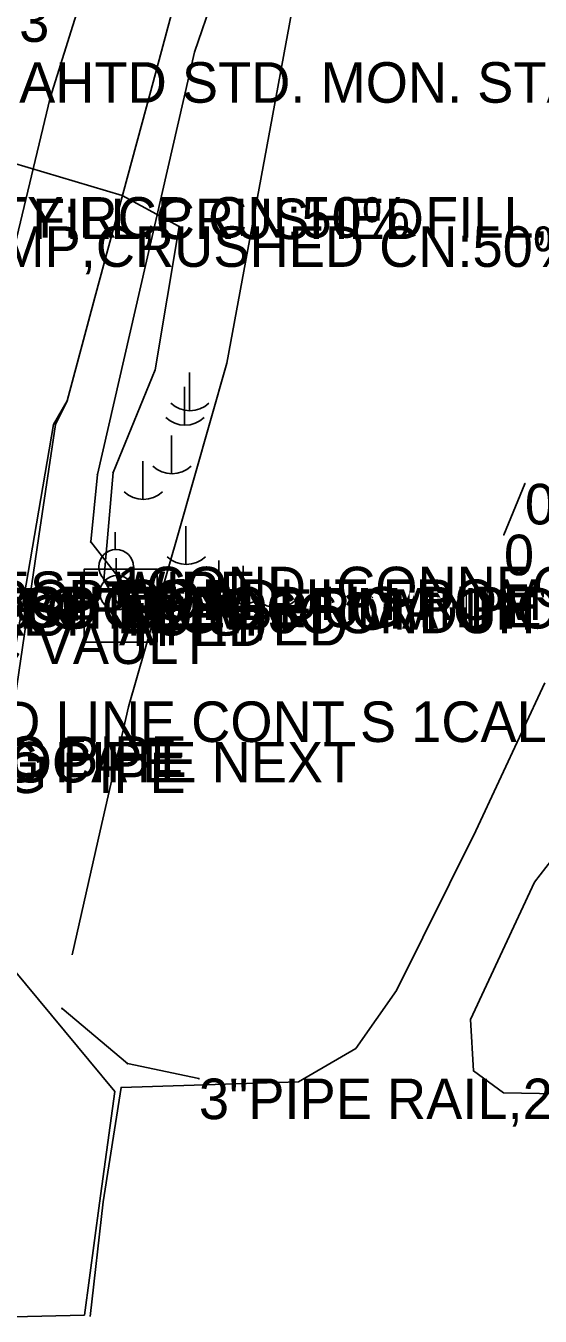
# Model space of a CAD drawing. Extents: x 997398 to 1003416, y 334596 to 337085.
# Drawn here: x 999274.2 to 999337.6, y 335481.5 to 335640.6 of the extents above; entities that cross this region are included whole.
import ezdxf

# ---------------------------------------------------------------- set-up
doc = ezdxf.new("R2010")
doc.units = 0
for name, color, linetype in [('S_DITCHLINE', 7, 'Continuous'), ('S_EDGE_PAVEMENT', 7, 'Continuous'), ('S_ELECTRIC_UTILITIES_ANNOT', 7, 'Continuous'), ('S_FENCE', 7, 'Continuous'), ('S_FENCE_ANNOT', 7, 'Continuous'), ('S_FIBER_OPTIC_CABLE', 7, 'Continuous'), ('S_FIBER_OPTIC_CABLE_ANNOT', 7, 'Continuous'), ('S_GAS_UTILITIES_ANNOT', 7, 'Continuous'), ('S_MANHOLE_ANNOT', 7, 'Continuous'), ('S_MISC_TOPO_POINT', 7, 'Continuous'), ('S_MSC_PT_SYM', 7, 'Continuous'), ('S_PAVEMENT_CROWN', 7, 'Continuous'), ('S_PRIMARY_CTL_ANNOT', 7, 'Continuous'), ('S_SANITARY_SEWER_ANNOT', 7, 'Continuous'), ('S_SIDE_DRAIN_ANNOT', 7, 'Continuous'), ('S_SIGN', 7, 'Continuous'), ('S_SIGN_ANNOT', 7, 'Continuous'), ('S_STORM_SEWER_ANNOT', 7, 'Continuous'), ('S_TELEPHONE_UTILITIES', 7, 'Continuous'), ('S_TELEPHONE_UTILITIES_ANNOT', 7, 'Continuous'), ('S_UTILITY_POLE', 7, 'Continuous'), ('S_UTILITY_POLE_ANNOT', 7, 'Continuous'), ('S_UTL_PT_SYM', 7, 'Continuous')]:
    doc.layers.add(name, color=color, linetype=linetype)

msp = doc.modelspace()

# ---------------------------------------------------------------- linework, layer by layer
at = {"layer": 'S_DITCHLINE'}
msp.add_lwpolyline([(999279.93, 335526.04), (999283.42, 335541.33), (999286.91, 335556.62), (999292.97, 335577.81), (999299.03, 335599), (999303, 335620.58), (999306.97, 335642.16), (999314.07, 335652.72)], dxfattribs=at)
at = {"layer": 'S_EDGE_PAVEMENT'}
for points in [[(999352.59, 335804.28), (999348.8, 335795.55), (999343.98, 335783.6), (999339.17, 335771.64), (999334.35, 335759.69), (999329.54, 335747.73), (999324.76, 335734.99), (999319.98, 335722.25), (999315.21, 335709.51), (999310.43, 335696.77), (999306.09, 335683.91), (999301.75, 335671.05), (999297.41, 335658.19), (999293.07, 335645.33), (999289.63, 335632.59), (999286.2, 335619.85), (999282.76, 335607.12), (999279.33, 335594.38)], [(999277.63, 335591.45), (999279.33, 335594.38)], [(999277.88, 335591.43), (999279.33, 335594.38)], [(999250.53, 335290.61), (999251.9, 335310.31), (999253.28, 335330), (999254.66, 335349.69), (999256.03, 335369.39), (999256.96, 335383.69), (999257.89, 335397.99), (999259.31, 335422.72), (999260.17, 335436.32), (999261.04, 335449.92), (999261.9, 335463.52), (999262.77, 335477.12), (999265.06, 335501.55), (999266.67, 335519.12), (999268.27, 335536.68), (999270.61, 335550.38), (999272.95, 335564.07), (999275.29, 335577.76), (999277.63, 335591.45)], [(999268.87, 335320.6), (999263.53, 335329.26), (999260.4, 335340), (999260.03, 335350.15), (999261.25, 335369.32), (999262.19, 335383.58), (999263.12, 335397.84), (999266.91, 335402.13), (999261.38, 335422.51), (999262.14, 335435.92), (999262.89, 335449.33), (999263.64, 335462.75), (999264.4, 335476.16), (999272.66, 335481.44), (999281.46, 335481.65), (999283.33, 335495.44), (999285.2, 335509.23), (999269.56, 335528.03), (999269.81, 335536.47), (999271.83, 335550.21), (999273.84, 335563.95), (999275.86, 335577.69), (999277.88, 335591.43)], [(999282.16, 335481.48), (999283.77, 335495.62), (999285.97, 335509.72), (999307.86, 335510.4), (999314.93, 335514.53), (999319.93, 335521.66), (999329.71, 335541.35), (999338.23, 335559.58)], [(999345.33, 335545.87), (999336.92, 335535.03), (999329.07, 335518.09), (999329.41, 335511.74), (999333.12, 335509.03), (999344.25, 335508.86)]]:
    msp.add_lwpolyline(points, dxfattribs=at)
at = {"layer": 'S_FENCE'}
for p, q in [((999286.76, 335512.65), (999278.7, 335519.45)), ((999295.57, 335510.8), (999286.76, 335512.65))]:
    msp.add_line(p, q, dxfattribs=at)
at = {"layer": 'S_FIBER_OPTIC_CABLE'}
for p, q in [((999295.04, 335637.34), (999313.68, 335692.48)), ((999283.06, 335585.29), (999295.04, 335637.34)), ((999286.13, 335619.67), (999256.41, 335628.49)), ((999293.13, 335615.87), (999286.13, 335619.67)), ((999290.19, 335598.19), (999293.13, 335615.87)), ((999285.01, 335585.53), (999290.19, 335598.19)), ((999282.24, 335576.97), (999283.06, 335585.29)), ((999283.84, 335572.27), (999285.01, 335585.53)), ((999285.88, 335572.34), (999282.24, 335576.97)), ((999285.71, 335569.2), (999283.84, 335572.27)), ((999285.67, 335571.14), (999285.71, 335569.2))]:
    msp.add_line(p, q, dxfattribs=at)
at = {"layer": 'S_MSC_PT_SYM'}
for points in [[(999335.75, 335584.13), (999335.75, 335584.18), (999335.75, 335584.13), (999335.7, 335584.13), (999335.75, 335584.13), (999335.75, 335584.08), (999335.75, 335584.13), (999335.8, 335584.13)], [(999333.17, 335577.86), (999333.17, 335577.91), (999333.17, 335577.86), (999333.12, 335577.86), (999333.17, 335577.86), (999333.17, 335577.81), (999333.17, 335577.86), (999333.22, 335577.86)], [(999278.7, 335519.45), (999278.7, 335519.5), (999278.7, 335519.45), (999278.65, 335519.45), (999278.7, 335519.45), (999278.7, 335519.4), (999278.7, 335519.45), (999278.75, 335519.45)], [(999286.76, 335512.65), (999286.76, 335512.7), (999286.76, 335512.65), (999286.71, 335512.65), (999286.76, 335512.65), (999286.76, 335512.6), (999286.76, 335512.65), (999286.81, 335512.65)], [(999295.57, 335510.8), (999295.57, 335510.85), (999295.57, 335510.8), (999295.52, 335510.8), (999295.57, 335510.8), (999295.57, 335510.75), (999295.57, 335510.8), (999295.62, 335510.8)]]:
    msp.add_lwpolyline(points, dxfattribs=at)
at = {"layer": 'S_PAVEMENT_CROWN'}
msp.add_lwpolyline([(999240.93, 335269.15), (999242.42, 335292.45), (999243.36, 335312.31), (999244.3, 335332.17), (999245.73, 335356.52), (999247.17, 335380.88), (999248.33, 335401.35), (999249.49, 335421.83), (999250.52, 335439.55), (999251.54, 335457.27), (999252.57, 335474.99), (999253.6, 335492.71), (999255.46, 335505.53), (999257.33, 335518.35), (999259.19, 335531.16), (999261.06, 335543.98), (999262.92, 335556.8), (999264.79, 335569.61), (999266.65, 335582.43), (999268.52, 335595.25), (999272.87, 335613.5), (999277.22, 335631.74), (999281.77, 335646.2)], dxfattribs=at)
at = {"layer": 'S_SIGN'}
msp.add_line((999333.17, 335577.86), (999335.75, 335584.13), dxfattribs=at)
at = {"layer": 'S_TELEPHONE_UTILITIES'}
msp.add_lwpolyline([(999281.42, 335564.61), (999281.42, 335573.61), (999290.42, 335573.61), (999290.42, 335564.61)], close=True, dxfattribs=at)
at = {"layer": 'S_UTILITY_POLE'}
for p, q in [((999294.4, 335597.85), (999294.4, 335593.12)), ((999293.78, 335596.08), (999293.78, 335591.35)), ((999292.2, 335590.09), (999292.2, 335585.36)), ((999288.67, 335586.92), (999288.67, 335582.19)), ((999293.95, 335578.9), (999293.95, 335574.17)), ((999285.24, 335576.05), (999285.24, 335578.16)), ((999285.37, 335572.85), (999285.37, 335574.96)), ((999298.02, 335574.67), (999298.02, 335569.95)), ((999301.04, 335574.04), (999301.04, 335569.32)), ((999305.12, 335573.56), (999305.12, 335568.83))]:
    msp.add_line(p, q, dxfattribs=at)
for centre in [(999285.37, 335573.91), (999285.49, 335570.71)]:
    msp.add_circle(centre, 2.13, dxfattribs=at)
for centre in [(999294.46, 335596.55), (999293.85, 335594.77), (999292.26, 335588.79), (999288.73, 335585.62), (999294.02, 335577.6), (999298.09, 335573.37), (999301.11, 335572.74), (999305.18, 335572.26)]:
    msp.add_arc(centre, 3.41, 226.3972, 313.6028, dxfattribs=at)
at = {"layer": 'S_UTL_PT_SYM'}
for points in [[(999295.04, 335637.34), (999295.04, 335637.39), (999295.04, 335637.34), (999294.99, 335637.34), (999295.04, 335637.34), (999295.04, 335637.29), (999295.04, 335637.34), (999295.09, 335637.34)], [(999286.13, 335619.67), (999286.13, 335619.72), (999286.13, 335619.67), (999286.08, 335619.67), (999286.13, 335619.67), (999286.13, 335619.62), (999286.13, 335619.67), (999286.18, 335619.67)], [(999293.13, 335615.87), (999293.13, 335615.92), (999293.13, 335615.87), (999293.08, 335615.87), (999293.13, 335615.87), (999293.13, 335615.82), (999293.13, 335615.87), (999293.18, 335615.87)], [(999290.19, 335598.19), (999290.19, 335598.24), (999290.19, 335598.19), (999290.14, 335598.19), (999290.19, 335598.19), (999290.19, 335598.14), (999290.19, 335598.19), (999290.24, 335598.19)], [(999283.06, 335585.29), (999283.06, 335585.34), (999283.06, 335585.29), (999283.01, 335585.29), (999283.06, 335585.29), (999283.06, 335585.24), (999283.06, 335585.29), (999283.11, 335585.29)], [(999285.01, 335585.53), (999285.01, 335585.58), (999285.01, 335585.53), (999284.96, 335585.53), (999285.01, 335585.53), (999285.01, 335585.48), (999285.01, 335585.53), (999285.06, 335585.53)], [(999282.24, 335576.97), (999282.24, 335577.02), (999282.24, 335576.97), (999282.19, 335576.97), (999282.24, 335576.97), (999282.24, 335576.92), (999282.24, 335576.97), (999282.29, 335576.97)], [(999283.84, 335572.27), (999283.84, 335572.32), (999283.84, 335572.27), (999283.79, 335572.27), (999283.84, 335572.27), (999283.84, 335572.22), (999283.84, 335572.27), (999283.89, 335572.27)], [(999285.88, 335572.34), (999285.88, 335572.39), (999285.88, 335572.34), (999285.83, 335572.34), (999285.88, 335572.34), (999285.88, 335572.29), (999285.88, 335572.34), (999285.93, 335572.34)], [(999285.67, 335571.14), (999285.67, 335571.19), (999285.67, 335571.14), (999285.62, 335571.14), (999285.67, 335571.14), (999285.67, 335571.09), (999285.67, 335571.14), (999285.72, 335571.14)], [(999285.71, 335569.2), (999285.71, 335569.25), (999285.71, 335569.2), (999285.66, 335569.2), (999285.71, 335569.2), (999285.71, 335569.15), (999285.71, 335569.2), (999285.76, 335569.2)]]:
    msp.add_lwpolyline(points, dxfattribs=at)

# ---------------------------------------------------------------- texts
at = {"layer": 'S_ELECTRIC_UTILITIES_ANNOT'}
for s, p in [('LOWEST WIRE', (999255.04, 335568.32)), ('CL48EW*32NSFOC VAULT', (999213.52, 335561.92))]:
    msp.add_text(s, height=5, dxfattribs=at).set_placement(p)
at = {"layer": 'S_FENCE_ANNOT'}
msp.add_text('3"PIPE RAIL,2.5\'H', height=5, dxfattribs=at).set_placement((999295.57, 335505.8))
at = {"layer": 'S_FIBER_OPTIC_CABLE_ANNOT'}
for s, p in [('CONDUIT FROM OH', (999285.88, 335567.34)), ('FEED FROM OH', (999285.67, 335566.14)), ('AT TPED', (999285.71, 335564.2))]:
    msp.add_text(s, height=5, dxfattribs=at).set_placement(p)
at = {"layer": 'S_GAS_UTILITIES_ANNOT'}
msp.add_text('1CALL SEZ DED LINE CONT S 1CALL', height=5, dxfattribs=at).set_placement((999224.76, 335552.3))
at = {"layer": 'S_MANHOLE_ANNOT'}
msp.add_text('TY:CONC BOTTOM OF MANHOLE', height=5, dxfattribs=at).set_placement((999241.48, 335566.28))
at = {"layer": 'S_MISC_TOPO_POINT'}
for p in [(999240.51, 335566.44), (999196.73, 335548), (999195.72, 335547.31), (999196.62, 335546)]:
    msp.add_text('SURFACE SHOT FOR UG PIPE', height=5, dxfattribs=at).set_placement(p)
at = {"layer": 'S_PRIMARY_CTL_ANNOT'}
for s, p in [('PN:3', (999262.27, 335638.62)), ('PD:AHTD STD. MON. STAMPED PN 3', (999262.27, 335631.12))]:
    msp.add_text(s, height=5, dxfattribs=at).set_placement(p)
at = {"layer": 'S_SANITARY_SEWER_ANNOT'}
msp.add_text('DI:6 TY:PVC TO W,C/N LOCATE NEXT', height=5, dxfattribs=at).set_placement((999195.72, 335547.31))
at = {"layer": 'S_SIDE_DRAIN_ANNOT'}
for s, p in [('CN:50% FILL,CRUSHED', (999248.25, 335614.3)), ('DI:18 TY:RCP CN:50% FILL,CONT.N', (999252.48, 335614.48)), ('DI:24 TY:CMP,CRUSHED CN:50% FIL', (999237.91, 335610.88)), ('CN:0% FILL', (999241.18, 335565.41))]:
    msp.add_text(s, height=5, dxfattribs=at).set_placement(p)
at = {"layer": 'S_SIGN_ANNOT'}
for s, p in [('0', (999335.75, 335579.13)), ('0 PVILLE COMMUNITY PANTRY PERM. NUM.', (999333.17, 335572.86))]:
    msp.add_text(s, height=5, dxfattribs=at).set_placement(p)
at = {"layer": 'S_STORM_SEWER_ANNOT'}
for s, p in [('DI:18 TY:RCP TO N.', (999241.58, 335567.28)), ('DI:18 TY:RCP TO W.', (999240.51, 335566.44)), ('CL 2.0X2.0 GR8', (999241.48, 335566.28)), ('DI:18 TY:RCP TO S.', (999241.29, 335565.42))]:
    msp.add_text(s, height=5, dxfattribs=at).set_placement(p)
at = {"layer": 'S_TELEPHONE_UTILITIES'}
msp.add_text('T', height=6, rotation=360, dxfattribs=at).set_placement((999283.99, 335566.11))
at = {"layer": 'S_TELEPHONE_UTILITIES_ANNOT'}
msp.add_text('TPED', height=5, dxfattribs=at).set_placement((999286.15, 335564.13))
at = {"layer": 'S_UTILITY_POLE_ANNOT'}
for s, p in [('1COND.,CONNECT TO ADJ PP', (999285.37, 335568.91)), ('1LGT,3CONDUIT,OHE NNE.. ..NE,S,', (999285.49, 335565.71))]:
    msp.add_text(s, height=5, dxfattribs=at).set_placement(p)

doc.saveas('drawing.dxf')
